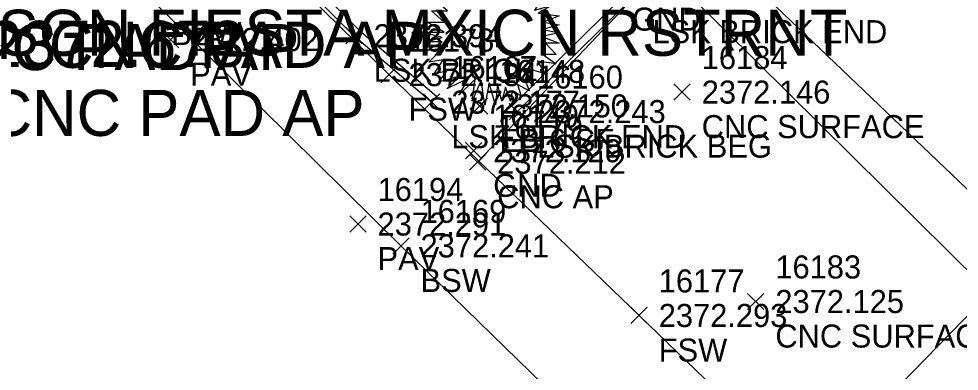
# Model space of a CAD drawing. Extents: x 2377639 to 2379738, y 729875 to 732734.
# Drawn here: x 2378616.34 to 2378657.12, y 730741.64 to 730756.94 of the extents above; entities that cross this region are included whole.
import ezdxf

# ---------------------------------------------------------------- set-up
doc = ezdxf.new("R2010")
doc.units = 0
for name, color, linetype in [('Default', 7, 'Continuous'), ('TOPO_CURBGTR_Back-of-Curb', 7, 'Continuous'), ('TOPO_CURBGTR_Lip-of-Gutter', 7, 'Continuous'), ('TOPO_DATA_Elevations', 7, 'Continuous'), ('TOPO_LNDSCP_Misc', 7, 'Continuous'), ('TOPO_LNDSCP_Tree', 7, 'Continuous'), ('TOPO_SW_Back', 7, 'Continuous')]:
    doc.layers.add(name, color=color, linetype=linetype)

# ---------------------------------------------------------------- blocks, each defined once
blk = doc.blocks.new('EB_2')
at = {"layer": 'Default'}
for p, q in [((-0.0157, 0.0948), (-0.007, 0.1296)), ((-0.007, 0.1296), (0.0007, 0.0899)), ((0.0007, 0.0899), (0.0153, 0.1229)), ((0.0153, 0.1229), (0.0153, 0.0889)), ((-0.0622, 0.1093), (-0.0361, 0.087)), ((-0.0516, 0.0773), (-0.0622, 0.1093)), ((-0.0361, 0.087), (-0.0429, 0.1199)), ((-0.0429, 0.1199), (-0.0157, 0.0948)), ((0.0153, 0.0889), (0.0405, 0.1112)), ((0.0405, 0.1112), (0.0221, 0.0822)), ((-0.0787, 0.0608), (-0.0981, 0.0889)), ((-0.0981, 0.0889), (-0.0661, 0.0686)), ((-0.0661, 0.0686), (-0.0787, 0.1015)), ((-0.0787, 0.1015), (-0.0516, 0.0773)), ((0.0221, 0.0822), (0.055, 0.1035)), ((0.055, 0.1035), (0.0366, 0.0773)), ((0.0366, 0.0773), (0.0715, 0.0948)), ((0.0715, 0.0948), (0.0599, 0.0657)), ((0.0599, 0.0657), (0.086, 0.0734)), ((0.086, 0.0734), (0.0724, 0.0521)), ((-0.0874, 0.0511), (-0.1088, 0.0686)), ((-0.1088, 0.0686), (-0.0787, 0.0608)), ((0.0724, 0.0521), (0.1035, 0.0608)), ((0.1035, 0.0608), (0.0792, 0.0463)), ((-0.0932, 0.0298), (-0.1165, 0.0511)), ((-0.1165, 0.0511), (-0.0874, 0.0511)), ((0.0792, 0.0463), (0.118, 0.0415)), ((0.118, 0.0415), (0.0889, 0.0298)), ((-0.0932, 0.0114), (-0.1243, 0.0298)), ((-0.1243, 0.0298), (-0.0932, 0.0298)), ((0.118, 0.025), (0.088, 0.0163)), ((0.0889, 0.0298), (0.118, 0.025)), ((-0.0971, 0.0017), (-0.1339, 0.0114)), ((-0.1339, 0.0114), (-0.0932, 0.0114)), ((-0.1291, -0.006), (-0.0971, 0.0017)), ((0.118, 0.0104), (0.086, 0.0037)), ((0.086, 0.0037), (0.118, -0.0089)), ((0.088, 0.0163), (0.118, 0.0104)), ((-0.0971, -0.006), (-0.1291, -0.006)), ((-0.1262, -0.0225), (-0.0971, -0.006)), ((0.118, -0.0089), (0.0928, -0.0089)), ((0.0928, -0.0089), (0.1122, -0.0293)), ((-0.0952, -0.0177), (-0.1262, -0.0225)), ((-0.1213, -0.0438), (-0.0952, -0.0177)), ((0.1122, -0.0293), (0.088, -0.0293)), ((0.088, -0.0293), (0.1122, -0.0467)), ((-0.0952, -0.039), (-0.1213, -0.0438)), ((-0.1117, -0.0651), (-0.0952, -0.039)), ((0.1122, -0.0467), (0.0773, -0.0419)), ((0.0773, -0.0419), (0.0928, -0.0651)), ((-0.0884, -0.0603), (-0.1117, -0.0651)), ((-0.1029, -0.0797), (-0.0884, -0.0603)), ((0.0928, -0.0651), (0.0628, -0.0564)), ((0.0628, -0.0564), (0.0715, -0.0865)), ((-0.0642, -0.07), (-0.1029, -0.0797)), ((-0.0884, -0.0923), (-0.0642, -0.07)), ((-0.0477, -0.0729), (-0.0884, -0.0923)), ((-0.0661, -0.1039), (-0.0477, -0.0729)), ((-0.0361, -0.0748), (-0.0661, -0.1039)), ((-0.0419, -0.1155), (-0.0361, -0.0748)), ((-0.0254, -0.0768), (-0.0419, -0.1155)), ((-0.0186, -0.1223), (-0.0254, -0.0768)), ((-0.0109, -0.0816), (-0.0186, -0.1223)), ((0.0007, -0.1223), (-0.0109, -0.0816)), ((0.0046, -0.0826), (0.0007, -0.1223)), ((0.0124, -0.1155), (0.0046, -0.0826)), ((0.0628, -0.0961), (0.0414, -0.0845)), ((0.0414, -0.0845), (0.0482, -0.1058)), ((0.0715, -0.0865), (0.055, -0.0748)), ((0.055, -0.0748), (0.0628, -0.0961)), ((0.0192, -0.0894), (0.0124, -0.1155)), ((0.0288, -0.1155), (0.0192, -0.0894)), ((0.0318, -0.0961), (0.0288, -0.1155)), ((0.0482, -0.1058), (0.0318, -0.0961))]:
    blk.add_line(p, q, dxfattribs=at)

msp = doc.modelspace()

# ---------------------------------------------------------------- linework, layer by layer
at = {"layer": 'TOPO_CURBGTR_Back-of-Curb'}
msp.add_line((2378643.981, 730759.404), (2378658.449, 730745.047), dxfattribs=at)
at = {"layer": 'TOPO_CURBGTR_Lip-of-Gutter'}
msp.add_lwpolyline([(2378631.019, 730774.066), (2378645.057, 730761.416), (2378645.057, 730761.416), (2378660.29, 730746.843)], dxfattribs=at)
at = {"layer": 'TOPO_DATA_Elevations'}
for p, q in [((2378630.518, 730755.851), (2378631.226, 730756.559)), ((2378630.518, 730756.559), (2378631.226, 730755.851)), ((2378630.518, 730755.851), (2378631.226, 730756.559)), ((2378630.518, 730756.559), (2378631.226, 730755.851)), ((2378622.563, 730755.685), (2378623.271, 730756.393)), ((2378622.563, 730756.393), (2378623.271, 730755.685)), ((2378622.563, 730755.685), (2378623.271, 730756.393)), ((2378622.563, 730756.393), (2378623.271, 730755.685)), ((2378632.031, 730754.161), (2378632.739, 730754.869)), ((2378632.031, 730754.869), (2378632.739, 730754.161)), ((2378632.031, 730754.161), (2378632.739, 730754.869)), ((2378632.031, 730754.869), (2378632.739, 730754.161)), ((2378644.744, 730753.403), (2378645.452, 730754.111)), ((2378644.744, 730754.111), (2378645.452, 730753.403)), ((2378644.744, 730753.403), (2378645.452, 730754.111)), ((2378644.744, 730754.111), (2378645.452, 730753.403)), ((2378633.885, 730752.968), (2378634.593, 730753.676)), ((2378633.885, 730753.676), (2378634.593, 730752.968)), ((2378633.885, 730752.968), (2378634.593, 730753.676)), ((2378633.885, 730753.676), (2378634.593, 730752.968)), ((2378635.969, 730752.803), (2378636.677, 730753.511)), ((2378635.969, 730753.511), (2378636.677, 730752.803)), ((2378635.969, 730752.803), (2378636.677, 730753.511)), ((2378635.969, 730753.511), (2378636.677, 730752.803)), ((2378637.605, 730752.556), (2378638.313, 730753.264)), ((2378637.605, 730753.264), (2378638.313, 730752.556)), ((2378637.605, 730752.556), (2378638.313, 730753.264)), ((2378637.605, 730753.264), (2378638.313, 730752.556)), ((2378635.702, 730750.856), (2378636.41, 730751.564)), ((2378635.702, 730751.564), (2378636.41, 730750.856)), ((2378635.702, 730750.856), (2378636.41, 730751.564)), ((2378635.702, 730751.564), (2378636.41, 730750.856)), ((2378635.876, 730750.36), (2378636.584, 730751.068)), ((2378635.876, 730751.068), (2378636.584, 730750.36)), ((2378635.876, 730750.36), (2378636.584, 730751.068)), ((2378635.876, 730751.068), (2378636.584, 730750.36)), ((2378630.687, 730747.674), (2378631.395, 730748.382)), ((2378630.687, 730748.382), (2378631.395, 730747.674)), ((2378630.687, 730747.674), (2378631.395, 730748.382)), ((2378630.687, 730748.382), (2378631.395, 730747.674)), ((2378632.551, 730746.725), (2378633.259, 730747.433)), ((2378632.551, 730747.433), (2378633.259, 730746.725)), ((2378632.551, 730746.725), (2378633.259, 730747.433)), ((2378632.551, 730747.433), (2378633.259, 730746.725)), ((2378647.937, 730744.311), (2378648.645, 730745.019)), ((2378647.937, 730745.019), (2378648.645, 730744.311)), ((2378647.937, 730744.311), (2378648.645, 730745.019)), ((2378647.937, 730745.019), (2378648.645, 730744.311)), ((2378642.88, 730743.704), (2378643.588, 730744.412)), ((2378642.88, 730744.412), (2378643.588, 730743.704)), ((2378642.88, 730743.704), (2378643.588, 730744.412)), ((2378642.88, 730744.412), (2378643.588, 730743.704))]:
    msp.add_line(p, q, dxfattribs=at)
at = {"layer": 'TOPO_LNDSCP_Misc'}
msp.add_lwpolyline([(2378621.893, 730765.431), (2378624.76, 730762.767), (2378631.098, 730756.45), (2378634.456, 730753.575), (2378634.239, 730753.322), (2378630.872, 730756.205), (2378624.529, 730762.527), (2378621.659, 730765.194)], dxfattribs=at)
msp.add_lwpolyline([(2378642.964, 730757.88), (2378642.729, 730758.116), (2378637.724, 730753.146), (2378637.959, 730752.91)], close=True, dxfattribs=at)
at = {"layer": 'TOPO_SW_Back'}
msp.add_line((2378636.277, 730750.764), (2378644.226, 730759.161), dxfattribs=at)
for points in [[(2378658.449, 730745.047), (2378650.577, 730736.964), (2378643.234, 730744.058), (2378632.385, 730754.515), (2378614.685, 730771.869), (2378614.791, 730771.978)], [(2378618.352, 730761.502), (2378632.905, 730747.079), (2378632.905, 730747.079), (2378643.617, 730736.636), (2378647.224, 730733.212), (2378644.795, 730730.797)]]:
    msp.add_lwpolyline(points, dxfattribs=at)

# ---------------------------------------------------------------- block references
at = {"layer": 'TOPO_LNDSCP_Tree', "xscale": 23.622, "yscale": 23.622}
msp.add_blockref('EB_2', (2378636.986, 730756.085), dxfattribs=at)

# ---------------------------------------------------------------- texts
at = {"layer": 'TOPO_DATA_Elevations'}
for s, height, p in [('SGN FIESTA MXICN RSTRNT', 2, (2378615.422, 730755.333)), ('GND', 1, (2378642.937, 730756.425)), ('GND', 1, (2378642.937, 730756.425)), ('LSK BRICK END', 1, (2378643.818, 730755.88)), ('LSK BRICK END', 1, (2378643.818, 730755.88)), ('CNC PAD AP', 2, (2378612.161, 730754.709)), ('2372.673', 2, (2378614.983, 730754.853)), ('CNC PAD AP', 2, (2378617.645, 730754.808)), ('BSW', 1, (2378622.944, 730755.797)), ('BSW', 1, (2378622.944, 730755.797)), ('2372.402', 1, (2378623.771, 730755.539)), ('2372.402', 1, (2378623.771, 730755.539)), ('2372.394', 1, (2378631.726, 730755.705)), ('2372.394', 1, (2378631.726, 730755.705)), ('16178', 1, (2378633.239, 730755.515)), ('16178', 1, (2378633.239, 730755.515)), ('16184', 1, (2378645.952, 730754.757)), ('16184', 1, (2378645.952, 730754.757)), ('16167', 1, (2378635.093, 730754.322)), ('16167', 1, (2378635.093, 730754.322)), ('PAV', 1, (2378623.771, 730754.039)), ('PAV', 1, (2378623.771, 730754.039)), ('LSK BRICK', 1, (2378631.726, 730754.205)), ('LSK BRICK', 1, (2378631.726, 730754.205)), ('2372.134', 1, (2378633.239, 730754.015)), ('2372.134', 1, (2378633.239, 730754.015)), ('16148', 1, (2378637.177, 730754.157)), ('16148', 1, (2378637.177, 730754.157)), ('16160', 1, (2378638.813, 730753.91)), ('16160', 1, (2378638.813, 730753.91)), ('2372.146', 1, (2378645.952, 730753.257)), ('2372.146', 1, (2378645.952, 730753.257)), ('CNC PAD AP', 2, (2378614.983, 730751.853)), ('2372.177', 1, (2378635.093, 730752.822)), ('2372.177', 1, (2378635.093, 730752.822)), ('2372.150', 1, (2378637.177, 730752.657)), ('2372.150', 1, (2378637.177, 730752.657)), ('FSW', 1, (2378633.239, 730752.515)), ('FSW', 1, (2378633.239, 730752.515)), ('16149', 1, (2378636.91, 730752.21)), ('16149', 1, (2378636.91, 730752.21)), ('2372.243', 1, (2378638.813, 730752.41)), ('2372.243', 1, (2378638.813, 730752.41)), ('16179', 1, (2378637.084, 730751.714)), ('16179', 1, (2378637.084, 730751.714)), ('CNC SURFACE', 1, (2378645.952, 730751.757)), ('CNC SURFACE', 1, (2378645.952, 730751.757)), ('LSK BRICK END', 1, (2378635.093, 730751.322)), ('LSK BRICK END', 1, (2378635.093, 730751.322)), ('EB 6 SF', 1, (2378637.177, 730751.157)), ('EB 6 SF', 1, (2378637.177, 730751.157)), ('2372.129', 1, (2378636.91, 730750.71)), ('2372.129', 1, (2378636.91, 730750.71)), ('LSK BRICK BEG', 1, (2378638.813, 730750.91)), ('LSK BRICK BEG', 1, (2378638.813, 730750.91)), ('2372.212', 1, (2378637.084, 730750.214)), ('2372.212', 1, (2378637.084, 730750.214)), ('16194', 1, (2378631.895, 730749.028)), ('16194', 1, (2378631.895, 730749.028)), ('GND', 1, (2378636.91, 730749.21)), ('GND', 1, (2378636.91, 730749.21)), ('CNC AP', 1, (2378637.084, 730748.714)), ('CNC AP', 1, (2378637.084, 730748.714)), ('16169', 1, (2378633.759, 730748.079)), ('16169', 1, (2378633.759, 730748.079)), ('2372.291', 1, (2378631.895, 730747.528)), ('2372.291', 1, (2378631.895, 730747.528)), ('2372.241', 1, (2378633.759, 730746.579)), ('2372.241', 1, (2378633.759, 730746.579)), ('PAV', 1, (2378631.895, 730746.028)), ('PAV', 1, (2378631.895, 730746.028)), ('16183', 1, (2378649.145, 730745.665)), ('16183', 1, (2378649.145, 730745.665)), ('BSW', 1, (2378633.759, 730745.079)), ('BSW', 1, (2378633.759, 730745.079)), ('16177', 1, (2378644.088, 730745.058)), ('16177', 1, (2378644.088, 730745.058)), ('2372.125', 1, (2378649.145, 730744.165)), ('2372.125', 1, (2378649.145, 730744.165)), ('2372.293', 1, (2378644.088, 730743.558)), ('2372.293', 1, (2378644.088, 730743.558)), ('CNC SURFACE', 1, (2378649.145, 730742.665)), ('CNC SURFACE', 1, (2378649.145, 730742.665)), ('FSW', 1, (2378644.088, 730742.058)), ('FSW', 1, (2378644.088, 730742.058))]:
    msp.add_text(s, height=height, dxfattribs=at).set_placement(p)

doc.saveas('drawing.dxf')
